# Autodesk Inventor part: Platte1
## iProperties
Created: 2007-03
Part Number: Platte1
Document SubType Name: Modeling
Designer: Sascha Fleischer
Author: Sascha Fleischer
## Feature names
1. Extrusion1
2. Extrusion2
